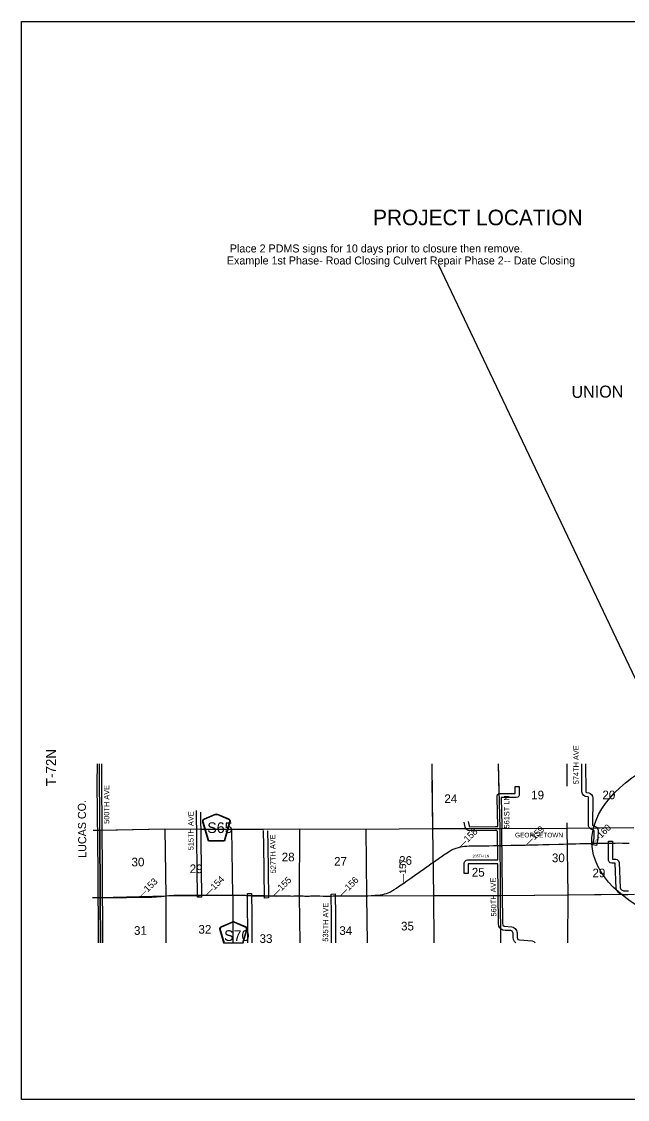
# Model space of a CAD drawing. Extents: x 10133 to 81668, y 5524 to 11018.
# Drawn here: x 13733 to 14867, y 7924 to 9944 of the extents above; entities that cross this region are included whole.
import ezdxf

# ---------------------------------------------------------------- set-up
doc = ezdxf.new("R2010")
doc.units = 0
for name, color, linetype in [('Default', 7, 'Continuous'), ('DisCLMLORText', 7, 'Continuous'), ('DisCLMLSUR', 7, 'Continuous'), ('DsnShtRevisedText', 7, 'Continuous'), ('dsnTextFinalPlan', 7, 'Continuous'), ('Level 3', 7, 'Continuous')]:
    doc.layers.add(name, color=color, linetype=linetype)

msp = doc.modelspace()

# ---------------------------------------------------------------- linework, layer by layer
at = {"layer": 'Default'}
for p, q in [((14110.8, 8217.6), (14147.7, 8217.6)), ((14111.8, 8217.6), (14146.7, 8217.6))]:
    msp.add_line(p, q, dxfattribs=at)
for points in [[(13876.3, 8217.6), (13876.3, 8221), (13876, 8351.9), (13874.4, 8516.1), (13874.5, 8552.7)], [(13880.4, 8217.6), (13880, 8302.5), (13878.8, 8428.4), (13878.2, 8552.7)], [(13882, 8552.7), (13881.9, 8516.1), (13883.5, 8351.9), (13883.8, 8221), (13883.8, 8217.6)], [(14500.6, 8552.7), (14500.9, 8528.8)], [(14500.6, 8552.7), (14502.1, 8431.5)], [(14625.3, 8552.7), (14626.5, 8497.2)], [(14625.3, 8552.7), (14627.9, 8432)], [(14753.5, 8552.7), (14753.6, 8511.4)], [(14753.5, 8552.7), (14753.5, 8521.6)], [(14788.9, 8552.7), (14789.5, 8500.6), (14790.6, 8499.1), (14795.1, 8498.5), (14797.4, 8497.5), (14799.6, 8495.7), (14801.5, 8492.3), (14802.1, 8488.5), (14801.9, 8437.8), (14802.7, 8436.8), (14805.7, 8436.2), (14809, 8434.4), (14811.2, 8431.7), (14812.3, 8428.4), (14812, 8412.7), (14809.5, 8399.7), (14802.1, 8400.9), (14804.6, 8413.4), (14804.9, 8427.3), (14803.8, 8428.9), (14800.7, 8429.6), (14797.9, 8430.9), (14795.6, 8433.6), (14794.5, 8436.4), (14794.2, 8440), (14794.5, 8489.6), (14793.4, 8491.1), (14788.1, 8492), (14785.4, 8493.6), (14783, 8496.7), (14782, 8500.4), (14781.6, 8552.7)], [(14501, 8521.3), (14502.1, 8431.5)], [(14568.7, 8444.8), (14570.7, 8436.7), (14571.6, 8435.2), (14620.4, 8435.7), (14624.3, 8435.3), (14623.4, 8489.2), (14623.4, 8492.8), (14624.1, 8495.2), (14625.7, 8496.9), (14628.2, 8497.6), (14657, 8497.4), (14656.9, 8510.3), (14664.4, 8510.2), (14664.5, 8495), (14663.6, 8492.4), (14661.9, 8490.8), (14658.5, 8489.9), (14630.9, 8490.1), (14631.8, 8436.8), (14631.1, 8428.7), (14631.6, 8424.6), (14633, 8254.2), (14633.8, 8250.9), (14636.6, 8248.5), (14650.8, 8247.8), (14653.2, 8246.9), (14656.8, 8244.4), (14659.4, 8240.6), (14660.3, 8238.2), (14660.7, 8236.2), (14660.5, 8227.8), (14661, 8225.4), (14662.1, 8224), (14665.3, 8223.3), (14688.8, 8221.4), (14692, 8219.9), (14694.4, 8217.6)], [(14067.6, 8462.2), (14069.2, 8303.2), (14061.7, 8303.2), (14060.1, 8465.6)], [(13866.3, 8428.4), (13875.1, 8428.4)], [(13866.3, 8428.4), (13878.8, 8428.4)], [(13878.8, 8428.4), (14000.7, 8431.1)], [(13878.8, 8428.4), (13880, 8302.5)], [(13882.6, 8428.5), (14000.7, 8431.1)], [(14000.7, 8431.1), (14060.3, 8430.8)], [(14000.7, 8431.1), (14002.9, 8305.5)], [(14000.7, 8431.1), (14002.9, 8305.5)], [(14000.7, 8431.1), (14126.4, 8430.4)], [(14067.8, 8430.7), (14126.4, 8430.4)], [(14126.4, 8430.4), (14252.8, 8431.1)], [(14126.4, 8430.4), (14185.7, 8430.7)], [(14128.3, 8306.9), (14126.4, 8430.4)], [(14128.3, 8306.9), (14126.4, 8430.4)], [(14193.1, 8427.7), (14193, 8425.2), (14193.7, 8401.8), (14195, 8301.7), (14187.5, 8301.4), (14186.2, 8401.7), (14185.5, 8425.1), (14185.5, 8428.1)], [(14193.2, 8430.8), (14252.8, 8431.1)], [(14252.8, 8431.1), (14252.7, 8305)], [(14252.8, 8431.1), (14252.7, 8305)], [(14252.8, 8431.1), (14377.5, 8430.4)], [(14252.8, 8431.1), (14377.5, 8430.4)], [(14377.5, 8430.4), (14502.1, 8431.5)], [(14377.5, 8430.4), (14502.1, 8431.5)], [(14377.5, 8430.4), (14378.2, 8305.8)], [(14377.5, 8430.4), (14378.2, 8305.8)], [(14502.1, 8431.5), (14627.9, 8432)], [(14502.1, 8431.5), (14564.7, 8431.8)], [(14502.1, 8431.5), (14503.8, 8306.2)], [(14502.1, 8431.5), (14503.8, 8306.2)], [(14658.3, 8217.6), (14658.2, 8217.6), (14655.6, 8220), (14653.5, 8224), (14653, 8227.5), (14653.2, 8235.7), (14651.5, 8239.1), (14648.5, 8240.6), (14637.9, 8240.7), (14633.8, 8241.5), (14630.2, 8243.7), (14628.3, 8245.7), (14626.6, 8248.5), (14625.5, 8253.9), (14624.4, 8365.4), (14568.9, 8365.3), (14568.7, 8347.4), (14561.2, 8347.5), (14561.5, 8367.4), (14562.7, 8370.2), (14565.4, 8372.3), (14567.4, 8372.8), (14624.4, 8372.9), (14624, 8426.1), (14621.7, 8428.1), (14620.4, 8428.2), (14571.2, 8427.7), (14567.9, 8428.6), (14565.8, 8430.3), (14563.5, 8434.5), (14561.4, 8443.4)], [(14627.9, 8432), (14753.7, 8432.5)], [(14627.9, 8432), (14628.7, 8306.4)], [(14631.5, 8432), (14753.7, 8432.5)], [(14753.7, 8442.2), (14753.7, 8432.5)], [(14753.7, 8438.5), (14753.7, 8432.5)], [(14753.7, 8432.5), (14879.3, 8433.8)], [(14753.7, 8432.5), (14796, 8432.9)], [(14753.7, 8432.5), (14755.5, 8307.6)], [(14753.7, 8432.5), (14755.5, 8307.6)], [(14810.3, 8433.1), (14879.3, 8433.8)], [(14868.1, 8307.6), (14859.7, 8307.4), (14856.2, 8308.4), (14852.4, 8310.2), (14849.4, 8312.7), (14846.8, 8317.3), (14846.2, 8319.6), (14844.3, 8366.6), (14837.7, 8366.8), (14835.1, 8367.6), (14833, 8369.2), (14831.9, 8372), (14832, 8408.3), (14839.5, 8408.3), (14839.2, 8374.3), (14845.5, 8374.2), (14847.7, 8373.5), (14850.4, 8371.2), (14851.7, 8368.1), (14853.7, 8320.5), (14854.3, 8319), (14856.1, 8316.7), (14860.2, 8315), (14869.1, 8315)], [(13867.2, 8302.4), (13876.2, 8302.5)], [(13867.2, 8302.4), (13880, 8302.5)], [(13867.2, 8302.3), (13873.5, 8302.5), (13878.6, 8302.5), (13880, 8302.5)], [(13880, 8302.5), (14002.9, 8305.5)], [(13880, 8302.5), (13880.4, 8217.6)], [(13883.7, 8302.6), (14002.9, 8305.5)], [(14002.9, 8305.5), (14128.3, 8306.9)], [(14002.9, 8305.5), (14061.7, 8306.2)], [(14002.9, 8305.5), (14003, 8217.6)], [(14002.9, 8305.5), (14003, 8217.6)], [(14069.2, 8306.2), (14128.3, 8306.9)], [(14128.3, 8306.9), (14155.6, 8306.5)], [(14128.3, 8306.9), (14128.4, 8217.6)], [(14128.3, 8306.9), (14252.7, 8305)], [(14128.3, 8306.9), (14128.4, 8217.6)], [(14156.2, 8217.6), (14155.5, 8309.8), (14163, 8309.9), (14163.5, 8270.7), (14163.8, 8217.6)], [(14163.1, 8306.4), (14187.4, 8306)], [(14194.9, 8305.9), (14252.7, 8305)], [(14252.7, 8305), (14378.2, 8305.8)], [(14252.7, 8305), (14312.3, 8305.4)], [(14252.7, 8305), (14253.7, 8217.6)], [(14252.7, 8305), (14253.7, 8217.6)], [(14312.7, 8217.6), (14312.7, 8269), (14312.2, 8309), (14319.7, 8309.1), (14320.2, 8269), (14320.2, 8217.6)], [(14319.8, 8305.4), (14378.2, 8305.8)], [(14378.2, 8305.8), (14503.8, 8306.2)], [(14378.2, 8305.8), (14503.8, 8306.2)], [(14378.2, 8305.8), (14379.5, 8217.6)], [(14378.2, 8305.8), (14379.5, 8217.6)], [(14503.8, 8306.2), (14624.9, 8306.4)], [(14503.8, 8306.2), (14628.7, 8306.4)], [(14503.8, 8306.2), (14504.3, 8217.6)], [(14503.8, 8306.2), (14504.3, 8217.6)], [(14628.7, 8306.4), (14755.5, 8307.6)], [(14628.7, 8306.4), (14629.4, 8217.6)], [(14632.4, 8306.4), (14755.5, 8307.6)], [(14755.5, 8307.6), (14755.1, 8217.6)], [(14755.5, 8307.6), (14755.1, 8217.6)], [(14755.5, 8307.6), (14880.5, 8309)], [(14755.5, 8307.6), (14855.4, 8308.7)], [(14147.7, 8217.6), (14154.5, 8241), (14154.9, 8242.6), (14155, 8243.3), (14155, 8244.3), (14154.5, 8245.6), (14153.6, 8246.7), (14152.4, 8247.5), (14131.5, 8256.5), (14130.6, 8256.8), (14129.2, 8256.9), (14127.9, 8256.8), (14127, 8256.5), (14106.1, 8247.5), (14104.9, 8246.7), (14104, 8245.6), (14103.5, 8244.3), (14103.5, 8243.3), (14103.6, 8242.6), (14104, 8241), (14110.8, 8217.6)], [(14146.7, 8217.6), (14153.5, 8240.8), (14153.9, 8242.4), (14154, 8243.1), (14154, 8244), (14153.5, 8245.3), (14152.6, 8246.3), (14151.5, 8247.1), (14131.4, 8255.8), (14130.5, 8256), (14129.2, 8256.1), (14128, 8256), (14127.1, 8255.8), (14107, 8247.1), (14105.9, 8246.3), (14105, 8245.3), (14104.5, 8244), (14104.5, 8243.1), (14104.6, 8242.4), (14105, 8240.8), (14111.8, 8217.6)], [(14629.2, 8244.8), (14629.4, 8217.6)]]:
    msp.add_lwpolyline(points, dxfattribs=at)
for points in [[(14082.5, 8407.8), (14072.2, 8443.2), (14071.7, 8444.8), (14071.7, 8445.5), (14071.7, 8446.5), (14072.2, 8447.8), (14073.1, 8448.9), (14074.3, 8449.7), (14095.2, 8458.7), (14096.1, 8458.9), (14097.4, 8459.1), (14098.7, 8458.9), (14099.7, 8458.7), (14120.6, 8449.7), (14121.8, 8448.9), (14122.7, 8447.8), (14123.2, 8446.5), (14123.2, 8445.5), (14123.1, 8444.8), (14122.7, 8443.2), (14112.4, 8407.8)], [(14083.2, 8408.6), (14073.2, 8443), (14072.8, 8444.6), (14072.7, 8445.3), (14072.7, 8446.2), (14073.2, 8447.5), (14074.1, 8448.5), (14075.2, 8449.3), (14095.3, 8458), (14096.2, 8458.2), (14097.4, 8458.3), (14098.7, 8458.2), (14099.6, 8458), (14119.7, 8449.3), (14120.8, 8448.5), (14121.7, 8447.5), (14122.2, 8446.2), (14122.2, 8445.3), (14122.1, 8444.6), (14121.6, 8443), (14111.7, 8408.6)]]:
    msp.add_lwpolyline(points, close=True, dxfattribs=at)
at = {"layer": 'DisCLMLSUR'}
msp.add_line((14949.9, 8569.5), (14513.6, 9488.8), dxfattribs=at)
at = {"layer": 'DsnShtRevisedText'}
msp.add_lwpolyline([(13865.5, 8302.3), (13873.5, 8302.5), (13878.6, 8302.5), (13880, 8302.5), (13890, 8302.5), (13894, 8302.5), (13896.6, 8302.5), (13901.8, 8302.4), (13912, 8302.5), (13918.6, 8302.6), (13928.9, 8302.7), (13937.9, 8302.8), (13944.6, 8303), (13947.6, 8303), (13952.1, 8302.9), (13960.9, 8302.8), (13968.4, 8303), (13970.4, 8303), (13973.3, 8303.1), (13976.4, 8303.3), (13980.1, 8303.6), (13983.4, 8303.9), (13985.3, 8304), (13989.6, 8304.1), (13994.1, 8304.5), (13997.8, 8305), (13999.5, 8305.1), (14002.4, 8305.4), (14004, 8305.6), (14008.5, 8306.1), (14012.7, 8306.4), (14017.7, 8306.7), (14019.9, 8306.8), (14024, 8306.9), (14027.9, 8306.9), (14031.6, 8306.8), (14035.3, 8306.8), (14040, 8306.8), (14042.8, 8306.8), (14050.8, 8306.9), (14058.2, 8306.9), (14062.1, 8306.9), (14065.4, 8306.9), (14073, 8306.9), (14075.3, 8306.9), (14075.4, 8306.9), (14083, 8307), (14090.5, 8306.9), (14100.8, 8307), (14107.8, 8307), (14111.5, 8306.9), (14116.6, 8306.8), (14121.2, 8306.8), (14127.1, 8306.9), (14128.9, 8306.9), (14132.8, 8306.9), (14135.8, 8306.9), (14141.1, 8306.9), (14148, 8306.7), (14149.2, 8306.6), (14151.5, 8306.6), (14153.2, 8306.5), (14157.7, 8306.2), (14159.3, 8306.1), (14162.8, 8305.9), (14167.1, 8305.7), (14168.4, 8305.6), (14172.6, 8305.4), (14176.5, 8305.3), (14179.6, 8305.3), (14181, 8305.3), (14181.1, 8305.3), (14183.6, 8305.3), (14188.9, 8305.3), (14191.2, 8305.3), (14192.7, 8305.3), (14195.8, 8305.3), (14200.2, 8305.5), (14203.1, 8305.5), (14205.1, 8305.6), (14207.3, 8305.4), (14209.1, 8305.3), (14210.5, 8305.2), (14212.2, 8305.3), (14214.5, 8305.4), (14216.5, 8305.5), (14219.4, 8305.6), (14222, 8305.7), (14224.6, 8305.6), (14227.1, 8305.4), (14229.1, 8305.3), (14232.4, 8305.3), (14236, 8305.3), (14239.4, 8305.2), (14242.5, 8305.3), (14245.7, 8305.5), (14247.9, 8305.7), (14250.6, 8305.8), (14252.1, 8305.7), (14256.5, 8305.5), (14259.8, 8305.3), (14263.2, 8305.2), (14267.8, 8305.1), (14271.2, 8305.2), (14273.9, 8305.3), (14277.1, 8305.5), (14280.8, 8305.7), (14283.5, 8305.6), (14285.1, 8305.5), (14286.9, 8305.3), (14291.3, 8305.4), (14297.3, 8305.2), (14303.2, 8305.2), (14311.5, 8305.2), (14316, 8305.3), (14316.9, 8305.3), (14318.9, 8305.4), (14323.4, 8305.6), (14329.4, 8305.6), (14333.9, 8305.6), (14338.3, 8305.5), (14342.9, 8305.4), (14346.5, 8305.4), (14353, 8305.6), (14361.3, 8305.5), (14370.5, 8305.7), (14373.9, 8305.7), (14376.7, 8305.7), (14381, 8305.8), (14387.1, 8306), (14391.9, 8306.4), (14392.7, 8306.5), (14394.5, 8306.6), (14396.5, 8306.7), (14399.3, 8306.8), (14400.9, 8306.9), (14404.1, 8307.4), (14409, 8308.3), (14412.5, 8309.1), (14415.7, 8310.1), (14418.9, 8311.2), (14421.9, 8312.6), (14423.4, 8313.3), (14427.5, 8315.5), (14430.6, 8317.4), (14434.6, 8320), (14438.6, 8322.8), (14443.2, 8325.9), (14448.2, 8329.4), (14454.3, 8333.9), (14459.8, 8337.7), (14468.1, 8343.5), (14471, 8345.6), (14473.9, 8347.5), (14478.8, 8350.9), (14487.1, 8356.8), (14491.6, 8360), (14496, 8363.1), (14499.8, 8365.9), (14502.1, 8367.4), (14508.4, 8371.6), (14514.7, 8376), (14520.8, 8380.4), (14526.1, 8384.1), (14527.4, 8385), (14531.8, 8387.9), (14535.3, 8390.1), (14539.1, 8392.2), (14542.8, 8393.8), (14546.6, 8395.2), (14550.5, 8396.4), (14554.4, 8397.3), (14558.4, 8398.1), (14562.3, 8398.6), (14566.6, 8398.9), (14570.8, 8399), (14578.1, 8399.2), (14588.1, 8399.3), (14595.6, 8399.5), (14607.3, 8399.6), (14616.2, 8399.7), (14625.7, 8400), (14628, 8400.1), (14634.1, 8400), (14649.6, 8400.3), (14651.6, 8400.4), (14657.9, 8400.5), (14668, 8400.6), (14674.9, 8400.6), (14682.7, 8400.9), (14688.8, 8401), (14699.9, 8401.2), (14709, 8401.6), (14720.3, 8401.9), (14738.4, 8402.4), (14747.6, 8402.5), (14753.6, 8402.8), (14755.5, 8402.9), (14765.1, 8403), (14770.3, 8403.2), (14777.9, 8403.4), (14784.1, 8403.6), (14792.6, 8403.7), (14803.3, 8403.9), (14806.4, 8404), (14812.2, 8404.2), (14820.1, 8404.4), (14828.5, 8404.5), (14833.1, 8404.5), (14835.8, 8404.6), (14841.1, 8404.6), (14844.3, 8404.6), (14851, 8404.7), (14858.2, 8404.6), (14870.4, 8404.6)], dxfattribs=at)
at = {"layer": 'dsnTextFinalPlan'}
msp.add_ellipse((15267.1, 8422.1), major_axis=(466.5, 18.2), ratio=0.458759, dxfattribs=at)
at = {"layer": 'Level 3'}
msp.add_lwpolyline([(13732.5, 9944), (16867.5, 9944), (16867.5, 7924), (13732.5, 7924)], close=True, dxfattribs=at)

# ---------------------------------------------------------------- texts
at = {"layer": 'Default'}
for s, height, rotation, p in [('PROJECT LOCATION', 29.166, 0.002, (14390.9, 9562.3)), ('UNION', 22.5, 0.6231, (14762.6, 9238.6)), ('T-72N', 18.75, 90.2753, (13797.2, 8511.1)), ('574TH AVE', 10, 90, (14776.1, 8514.7)), ('500TH AVE', 10, 90, (13896.7, 8440.5)), ('24', 16.25, 0.0209, (14524.3, 8479.5)), ('561ST LN', 10, 90, (14646.1, 8431.8)), ('19', 16.25, 0.0218, (14686.9, 8486.4)), ('20', 16.25, 0.0225, (14820.3, 8486.5)), ('LUCAS CO.', 15, 90.5404, (13853.8, 8377)), ('515TH AVE', 10, 89.9328, (14054.6, 8391)), ('‒‒158', 12.5, 45, (14554.8, 8391.9)), ('GEORGETOWN', 8.75, 0.022, (14656.7, 8415.1)), ('‒‒159', 12.5, 45, (14679.7, 8396.2)), ('‒‒160', 12.5, 45, (14804.9, 8399.4)), ('‒‒160', 12.5, 45, (14804.9, 8399.4)), ('527TH AVE', 10, 91, (14208.9, 8347.8)), ('28', 16.25, 0.0187, (14219.7, 8370.2)), ('30', 16.25, 0.0218, (14725.7, 8368.6)), ('30', 16.25, 0.0172, (13938.4, 8360.8)), ('29', 16.25, 0.0178, (14047.4, 8348.1)), ('27', 16.25, 0.0194, (14317.8, 8362.1)), ('‒‒157', 12.5, 90, (14452.7, 8328.2)), ('26', 16.25, 0.0201, (14439.6, 8363.7)), ('205TH LN', 5, 0.3769, (14577.2, 8377.4)), ('‒‒154', 12.5, 45, (14080.5, 8302.5)), ('25', 16.25, 0.0211, (14575.7, 8341.7)), ('29', 16.25, 0.0225, (14801.7, 8340.3)), ('‒‒153', 12.5, 45, (13955.6, 8298.5)), ('‒‒155', 12.5, 45, (14206.3, 8301.1)), ('‒‒155', 12.5, 45, (14206.3, 8301.1)), ('‒‒156', 12.5, 45, (14332, 8301.2)), ('560TH AVE', 10, 91, (14621.8, 8266.9)), ('535TH AVE', 10, 89.8178, (14306.7, 8219.7)), ('31', 16.25, 0.0172, (13943, 8232.5)), ('32', 16.25, 0.0179, (14063.8, 8234.7)), ('34', 16.25, 0.0195, (14327.6, 8232.3)), ('35', 16.25, 0.0202, (14443.1, 8240.7)), ('33', 16.25, 0.0187, (14178.2, 8217.3))]:
    msp.add_text(s, height=height, rotation=rotation, dxfattribs=at).set_placement(p)
for s, p in [('S65', (14080.2, 8423.3)), ('S70', (14111.7, 8221.1))]:
    msp.add_text(s, height=20, dxfattribs=at).set_placement(p)
at = {"layer": 'DisCLMLORText'}
for s, p in [(' Place 2 PDMS signs for 10 days prior to closure then remove. ', (14117, 9511.3)), ('Example 1st Phase- Road Closing Culvert Repair Phase 2-- Date Closing    ', (14117, 9488.8))]:
    msp.add_text(s, height=15, dxfattribs=at).set_placement(p)

doc.saveas('drawing.dxf')
